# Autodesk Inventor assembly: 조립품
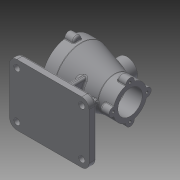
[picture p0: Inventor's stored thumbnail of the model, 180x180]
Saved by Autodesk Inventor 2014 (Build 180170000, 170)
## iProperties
Created: 2020-12
Part Number: 조립품
Document SubType Name: Assembly
Designer: kh
Author: kh
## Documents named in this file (2)
- C:\Users\kh\Desktop\701206V1026\조립품.iam
- C:\Users\kh\Desktop\701206V1026\본체.ipt
